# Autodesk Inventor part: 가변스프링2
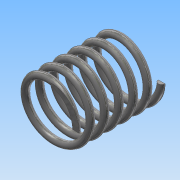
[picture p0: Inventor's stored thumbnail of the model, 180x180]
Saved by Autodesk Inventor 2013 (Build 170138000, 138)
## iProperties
Created: 2019-07
Part Number: 가변스프링2
Material: 강철, 탄소
Document SubType Name: Modeling
Designer: Administrator
Density: 7.87 g/cm^3
Mass: 7.79515 g
Surface Area: 20.0756 cm^2
Volume: 0.990489 cm^3
Author: Administrator
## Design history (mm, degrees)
sketch "스케치1"
  geometry: L1 (0, 0)-(0, 25.33); L2 (0, 25.33)-(16.881, 25.33); C1 r 1 at (8.5, 0)
  constraints: 4 end point, 1 centre point, 1 horizontal alignment, 1 perpendicular, 1 vertical
  dimensions: "d0" = 25.33013 distance of L1.start L1.end (derived); "d1" = 2 diameter of C1; "d2" = 17 diameter of C1.centre L1
feature "코일1" sketch "스케치1" pitch "d3" = 10; turns "d5" = 6; dims "d4" = 25.33013 (= d0), "d6" = 0, angle "d7" = 90 deg, angle "d8" = 90 deg, "d9" = 0, "d10" = 0
sketch "스케치2"
  geometry: L1 (0, 12.5)-(25.33, 12.5); L2 (25.33, 12.5)-(25.33, -12.5); L3 (25.33, -12.5)-(0, -12.5); L4 (0, -12.5)-(0, 12.5); 2 further points
  constraints: 8 end point, 2 parallel, 1 coincident, 1 horizontal, 1 midpoint, 1 perpendicular
  dimensions: "d11" = 25.33013 distance between parallel lines of L2 L4 (derived); "d13" = 25 distance between parallel lines of L1 L3
extrude "돌출1" sketch "스케치2" stored distance "d14" = 50; taper "d15" = 0 deg
node "솔리드1"
